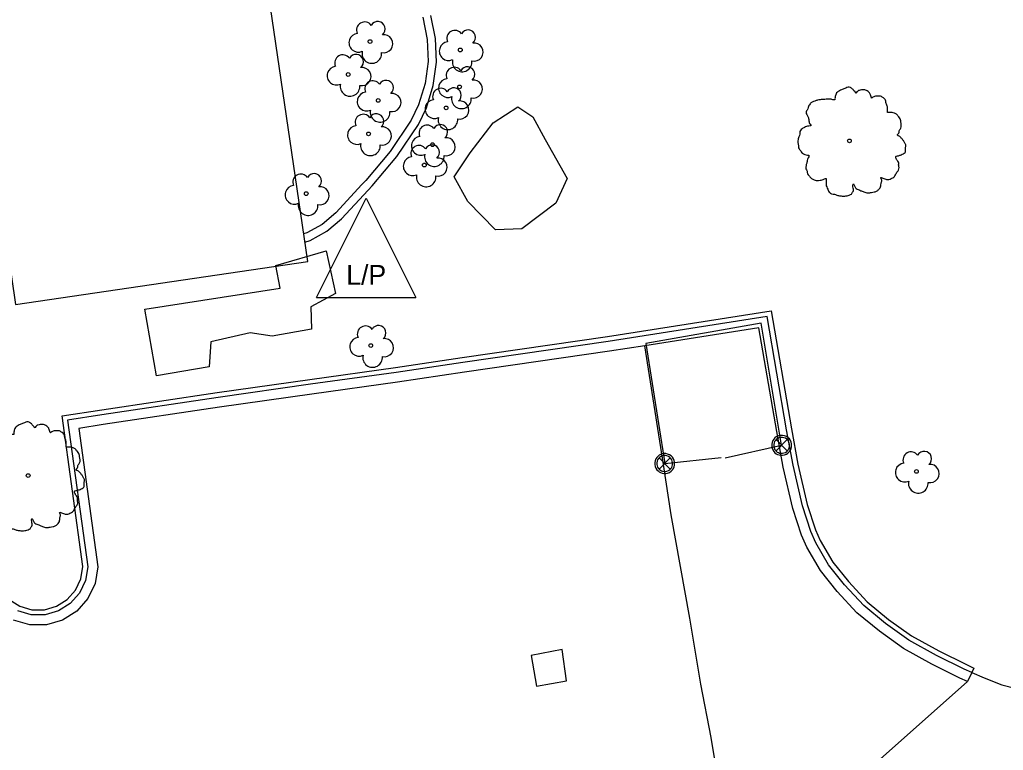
# Model space of a CAD drawing. Extents: x 2161152 to 2175754, y 602179 to 617749.
# Drawn here: x 2163635 to 2163733.9, y 606221.2 to 606294.7 of the extents above; entities that cross this region are included whole.
import ezdxf

# ---------------------------------------------------------------- set-up
doc = ezdxf.new("R2010")
doc.units = 0
for name, color, linetype in [('RD_EX_Bldg', 7, 'Continuous'), ('RD_EX_BldgApp_Post', 7, 'Continuous'), ('RD_EX_Conc_Curb', 7, 'Continuous'), ('RD_EX_Conc_Gutter', 7, 'Continuous'), ('RD_EX_DR_Inlet', 7, 'Continuous'), ('RD_EX_Fence_ChLk', 7, 'Continuous'), ('RD_EX_Fence_Gate', 7, 'Continuous'), ('RD_EX_Parking_Asphalt', 7, 'Continuous'), ('RD_EX_Parking_Conc', 7, 'Continuous'), ('RD_EX_UT', 7, 'Continuous'), ('RD_EX_VEG', 7, 'Continuous'), ('RD_EX_WALL_Retaining', 7, 'Continuous')]:
    doc.layers.add(name, color=color, linetype=linetype)

msp = doc.modelspace()

# ---------------------------------------------------------------- linework, layer by layer
at = {"layer": 'RD_EX_Bldg'}
msp.add_lwpolyline([(2163498.737, 606320.775), (2163509.48, 606247.58), (2163538.628, 606251.858), (2163536.268, 606267.933), (2163632.211, 606282.015), (2163634.559, 606266.023), (2163663.946, 606270.336), (2163653.216, 606343.448), (2163498.737, 606320.775)], dxfattribs=at)
at = {"layer": 'RD_EX_BldgApp_Post'}
for p, q in [((2163712.191, 606251.292), (2163711.057, 606252.426)), ((2163711.057, 606251.292), (2163712.191, 606252.426)), ((2163700.425, 606249.454), (2163699.291, 606250.588)), ((2163699.291, 606249.454), (2163700.425, 606250.588))]:
    msp.add_line(p, q, dxfattribs=at)
for points in [[(2163712.626, 606251.859), (2163712.614, 606252.013), (2163712.575, 606252.176), (2163712.503, 606252.34), (2163712.398, 606252.495), (2163712.26, 606252.633), (2163712.096, 606252.743), (2163711.914, 606252.818), (2163711.725, 606252.856), (2163711.54, 606252.858), (2163711.367, 606252.828), (2163711.213, 606252.773), (2163711.079, 606252.701), (2163710.953, 606252.604), (2163710.836, 606252.479), (2163710.737, 606252.326), (2163710.664, 606252.15), (2163710.626, 606251.958), (2163710.626, 606251.76), (2163710.664, 606251.567), (2163710.737, 606251.391), (2163710.836, 606251.239), (2163710.953, 606251.114), (2163711.079, 606251.017), (2163711.213, 606250.944), (2163711.367, 606250.89), (2163711.54, 606250.86), (2163711.725, 606250.861), (2163711.914, 606250.899), (2163712.096, 606250.974), (2163712.26, 606251.084), (2163712.398, 606251.222), (2163712.503, 606251.378), (2163712.575, 606251.542), (2163712.614, 606251.704), (2163712.626, 606251.859)], [(2163712.426, 606251.859), (2163712.416, 606251.982), (2163712.384, 606252.112), (2163712.327, 606252.243), (2163712.243, 606252.368), (2163712.133, 606252.478), (2163712.001, 606252.566), (2163711.856, 606252.626), (2163711.705, 606252.656), (2163711.556, 606252.658), (2163711.418, 606252.634), (2163711.295, 606252.59), (2163711.188, 606252.532), (2163711.087, 606252.455), (2163710.994, 606252.355), (2163710.914, 606252.233), (2163710.856, 606252.092), (2163710.826, 606251.938), (2163710.826, 606251.78), (2163710.856, 606251.626), (2163710.914, 606251.485), (2163710.994, 606251.363), (2163711.087, 606251.263), (2163711.188, 606251.185), (2163711.295, 606251.127), (2163711.418, 606251.083), (2163711.556, 606251.06), (2163711.705, 606251.061), (2163711.856, 606251.091), (2163712.001, 606251.151), (2163712.133, 606251.239), (2163712.243, 606251.349), (2163712.327, 606251.474), (2163712.384, 606251.605), (2163712.416, 606251.735), (2163712.426, 606251.859)], [(2163700.861, 606250.021), (2163700.849, 606250.176), (2163700.809, 606250.339), (2163700.738, 606250.502), (2163700.633, 606250.658), (2163700.495, 606250.796), (2163700.331, 606250.906), (2163700.148, 606250.981), (2163699.959, 606251.019), (2163699.774, 606251.02), (2163699.602, 606250.99), (2163699.448, 606250.936), (2163699.314, 606250.863), (2163699.188, 606250.767), (2163699.071, 606250.641), (2163698.972, 606250.489), (2163698.899, 606250.313), (2163698.861, 606250.12), (2163698.861, 606249.922), (2163698.899, 606249.73), (2163698.972, 606249.554), (2163699.071, 606249.401), (2163699.188, 606249.276), (2163699.314, 606249.18), (2163699.448, 606249.107), (2163699.602, 606249.052), (2163699.774, 606249.023), (2163699.959, 606249.024), (2163700.148, 606249.062), (2163700.331, 606249.137), (2163700.495, 606249.247), (2163700.633, 606249.385), (2163700.738, 606249.54), (2163700.809, 606249.704), (2163700.849, 606249.867), (2163700.861, 606250.021)], [(2163700.66, 606250.021), (2163700.651, 606250.145), (2163700.619, 606250.275), (2163700.562, 606250.406), (2163700.478, 606250.531), (2163700.368, 606250.641), (2163700.236, 606250.729), (2163700.09, 606250.789), (2163699.939, 606250.819), (2163699.791, 606250.821), (2163699.653, 606250.797), (2163699.53, 606250.753), (2163699.423, 606250.695), (2163699.322, 606250.617), (2163699.228, 606250.517), (2163699.149, 606250.395), (2163699.091, 606250.254), (2163699.06, 606250.101), (2163699.06, 606249.942), (2163699.091, 606249.788), (2163699.149, 606249.647), (2163699.228, 606249.525), (2163699.322, 606249.425), (2163699.423, 606249.348), (2163699.53, 606249.29), (2163699.653, 606249.246), (2163699.791, 606249.222), (2163699.939, 606249.224), (2163700.09, 606249.254), (2163700.236, 606249.314), (2163700.368, 606249.402), (2163700.478, 606249.512), (2163700.562, 606249.637), (2163700.619, 606249.768), (2163700.651, 606249.898), (2163700.66, 606250.021)]]:
    msp.add_lwpolyline(points, dxfattribs=at)
at = {"layer": 'RD_EX_Conc_Curb'}
for points in [[(2163633.915, 606236.335), (2163634.984, 606235.665), (2163636.196, 606235.317), (2163637.457, 606235.318), (2163638.669, 606235.668), (2163639.736, 606236.34), (2163640.575, 606237.282), (2163641.121, 606238.419), (2163641.329, 606239.656), (2163639.232, 606254.817), (2163643.225, 606255.429), (2163654.854, 606257.168), (2163664.155, 606258.492), (2163672.772, 606259.69), (2163679.494, 606260.684), (2163694.091, 606262.798), (2163710.561, 606265.383), (2163712.604, 606253.505), (2163713.261, 606249.97), (2163714.195, 606245.894), (2163715.034, 606243.372), (2163715.508, 606242.282), (2163716.758, 606240.115), (2163718.336, 606238.149), (2163720.224, 606236.108), (2163722.373, 606234.344), (2163724.676, 606232.7), (2163727.444, 606231.177), (2163730.204, 606229.806), (2163730.963, 606229.456), (2163730.754, 606229.002)], [(2163730.754, 606229.002), (2163729.989, 606229.355), (2163727.213, 606230.733), (2163724.409, 606232.276), (2163722.068, 606233.947), (2163719.88, 606235.744), (2163717.958, 606237.823), (2163716.344, 606239.831), (2163715.06, 606242.057), (2163714.567, 606243.194), (2163713.713, 606245.759), (2163712.771, 606249.868), (2163712.112, 606253.417), (2163710.152, 606264.812), (2163694.165, 606262.303), (2163679.567, 606260.189), (2163672.843, 606259.195), (2163664.225, 606257.996), (2163654.926, 606256.673), (2163643.23, 606254.924), (2163639.795, 606254.398), (2163641.835, 606239.649), (2163641.602, 606238.266), (2163640.995, 606237.002), (2163640.062, 606235.955), (2163638.876, 606235.207), (2163637.528, 606234.818), (2163636.126, 606234.816), (2163634.778, 606235.203)]]:
    msp.add_lwpolyline(points, dxfattribs=at)
at = {"layer": 'RD_EX_Conc_Gutter'}
msp.add_lwpolyline([(2163730.754, 606229.002), (2163730.335, 606228.094), (2163729.557, 606228.453), (2163726.749, 606229.847), (2163723.876, 606231.428), (2163721.46, 606233.153), (2163719.193, 606235.014), (2163717.2, 606237.169), (2163715.517, 606239.265), (2163714.166, 606241.607), (2163713.632, 606242.836), (2163712.749, 606245.489), (2163711.791, 606249.665), (2163711.127, 606253.241), (2163709.334, 606263.672), (2163697.858, 606261.871), (2163694.314, 606261.315), (2163679.711, 606259.2), (2163672.985, 606258.205), (2163664.364, 606257.006), (2163655.07, 606255.684), (2163643.381, 606253.935), (2163640.921, 606253.558), (2163642.847, 606239.634), (2163642.565, 606237.961), (2163641.836, 606236.442), (2163640.715, 606235.184), (2163639.289, 606234.286), (2163637.671, 606233.818), (2163635.986, 606233.816), (2163634.366, 606234.281)], dxfattribs=at)
at = {"layer": 'RD_EX_DR_Inlet'}
msp.add_lwpolyline([(2163686.439, 606230.705), (2163686.967, 606227.645), (2163689.979, 606228.165), (2163689.56, 606231.31), (2163686.439, 606230.705)], dxfattribs=at)
at = {"layer": 'RD_EX_Fence_ChLk'}
msp.add_lwpolyline([(2163711.624, 606251.859), (2163709.559, 606264.125), (2163697.954, 606262.1), (2163699.858, 606250.021)], dxfattribs=at)
at = {"layer": 'RD_EX_Fence_Gate'}
for p, q in [((2163705.952, 606250.605), (2163711.624, 606251.859)), ((2163699.858, 606250.021), (2163705.556, 606250.626))]:
    msp.add_line(p, q, dxfattribs=at)
at = {"layer": 'RD_EX_Parking_Asphalt'}
msp.add_lwpolyline([(2163730.754, 606229.002), (2163731.998, 606228.461), (2163733.791, 606227.776), (2163736.519, 606227.078), (2163738.725, 606226.876), (2163741.682, 606226.826), (2163744.188, 606226.765), (2163746.812, 606226.609), (2163748.382, 606226.712), (2163749.856, 606227.167), (2163751.292, 606227.813), (2163753.161, 606228.618)], dxfattribs=at)
at = {"layer": 'RD_EX_Parking_Conc'}
for points in [[(2163705.32, 606217.804), (2163704.529, 606222.462), (2163703.508, 606227.844), (2163702.398, 606234.461), (2163700.511, 606244.882), (2163699.752, 606249.926), (2163697.858, 606261.871)], [(2163730.335, 606228.094), (2163720.342, 606219.231), (2163711.857, 606211.684)]]:
    msp.add_lwpolyline(points, dxfattribs=at)
at = {"layer": 'RD_EX_UT'}
for p, q in [((2163664.836, 606266.716), (2163669.836, 606276.716)), ((2163669.836, 606276.716), (2163674.836, 606266.716)), ((2163664.836, 606266.716), (2163674.836, 606266.716))]:
    msp.add_line(p, q, dxfattribs=at)
at = {"layer": 'RD_EX_VEG'}
for points in [[(2163690.033, 606278.684), (2163688.894, 606276.222), (2163685.488, 606273.616), (2163682.834, 606273.522), (2163680.057, 606276.391), (2163678.68, 606278.852), (2163680.281, 606281.261), (2163682.617, 606284.286), (2163685.084, 606285.895), (2163686.583, 606284.902), (2163687.829, 606282.62), (2163690.033, 606278.684)], [(2163658.147, 606263.173), (2163654.189, 606262.266), (2163654.036, 606259.753), (2163648.742, 606258.829), (2163647.569, 606265.544), (2163661.167, 606267.67), (2163660.732, 606269.929), (2163665.791, 606271.423), (2163666.747, 606267.135), (2163664.266, 606265.776), (2163664.335, 606263.547), (2163660.382, 606262.834), (2163658.147, 606263.173)]]:
    msp.add_lwpolyline(points, dxfattribs=at)
for centre, radius in [((2163670.216, 606292.458), 0.188), ((2163679.3, 606291.614), 0.188), ((2163668.022, 606289.15), 0.188), ((2163679.227, 606287.898), 0.188), ((2163671.045, 606286.539), 0.188), ((2163677.868, 606285.789), 0.188), ((2163670.071, 606283.175), 0.188), ((2163718.445, 606282.468), 0.188), ((2163718.435, 606282.454), 0.000075), ((2163676.497, 606282.093), 0.188), ((2163675.68, 606280.045), 0.188), ((2163663.8, 606277.166), 0.188), ((2163670.291, 606261.887), 0.188), ((2163635.828, 606248.811), 0.188), ((2163635.819, 606248.797), 0.000075), ((2163725.182, 606249.231), 0.188)]:
    msp.add_circle(centre, radius, dxfattribs=at)
for centre, radius, start, end in [((2163669.675, 606293.619), 0.813, 34.97629, 204.75602), ((2163671, 606293.735), 0.746, 308.76261, 152.04674), ((2163669.043, 606292.342), 0.943, 96.45179, 294.73401), ((2163678.759, 606292.774), 0.813, 34.97629, 204.75602), ((2163680.084, 606292.89), 0.746, 308.76261, 152.04674), ((2163671.596, 606292.249), 0.914, 256.56668, 98.10463), ((2163678.127, 606291.497), 0.943, 96.45179, 294.73401), ((2163680.68, 606291.404), 0.914, 256.56668, 98.10463), ((2163670.4, 606291.261), 0.988, 166.88266, 5.75893), ((2163667.481, 606290.311), 0.813, 34.97629, 204.75602), ((2163668.806, 606290.427), 0.746, 308.76261, 152.04674), ((2163679.484, 606290.416), 0.988, 166.88266, 5.75893), ((2163666.849, 606289.034), 0.943, 96.45179, 294.73401), ((2163669.402, 606288.941), 0.914, 256.56668, 98.10463), ((2163678.686, 606289.059), 0.813, 34.97629, 204.75602), ((2163680.011, 606289.175), 0.746, 308.76261, 152.04674), ((2163670.504, 606287.699), 0.813, 34.97629, 204.75602), ((2163671.829, 606287.815), 0.746, 308.76261, 152.04674), ((2163678.054, 606287.782), 0.943, 96.45179, 294.73401), ((2163680.607, 606287.689), 0.914, 256.56668, 98.10463), ((2163668.206, 606287.953), 0.988, 166.88266, 5.75893), ((2163669.872, 606286.422), 0.943, 96.45179, 294.73401), ((2163672.425, 606286.329), 0.914, 256.56668, 98.10463), ((2163677.327, 606286.95), 0.813, 34.97629, 204.75602), ((2163678.651, 606287.066), 0.746, 308.76261, 152.04674), ((2163676.695, 606285.673), 0.943, 96.45179, 294.73401), ((2163679.411, 606286.701), 0.988, 166.88266, 5.75893), ((2163679.247, 606285.58), 0.914, 256.56668, 98.10463), ((2163671.229, 606285.341), 0.988, 166.88266, 5.75893), ((2163669.531, 606284.336), 0.813, 34.97629, 204.75602), ((2163670.855, 606284.452), 0.746, 308.76261, 152.04674), ((2163678.052, 606284.592), 0.988, 166.88266, 5.75893), ((2163668.899, 606283.059), 0.943, 96.45179, 294.73401), ((2163671.451, 606282.966), 0.914, 256.56668, 98.10463), ((2163675.956, 606283.254), 0.813, 34.97629, 204.75602), ((2163677.281, 606283.37), 0.746, 308.76261, 152.04674), ((2163675.324, 606281.976), 0.943, 96.45179, 294.73401), ((2163677.877, 606281.884), 0.914, 256.56668, 98.10463), ((2163670.256, 606281.978), 0.988, 166.88266, 5.75893), ((2163675.14, 606281.206), 0.813, 34.97629, 204.75602), ((2163676.464, 606281.322), 0.746, 308.76261, 152.04674), ((2163674.508, 606279.929), 0.943, 96.45179, 294.73401), ((2163676.681, 606280.896), 0.988, 166.88266, 5.75893), ((2163677.06, 606279.836), 0.914, 256.56668, 98.10463), ((2163663.259, 606278.326), 0.813, 34.97629, 204.75602), ((2163664.584, 606278.443), 0.746, 308.76261, 152.04674), ((2163675.864, 606278.848), 0.988, 166.88266, 5.75893), ((2163662.627, 606277.049), 0.943, 96.45179, 294.73401), ((2163665.18, 606276.956), 0.914, 256.56668, 98.10463), ((2163663.984, 606275.969), 0.988, 166.88266, 5.75893), ((2163669.75, 606263.048), 0.813, 34.97629, 204.75602), ((2163671.075, 606263.164), 0.746, 308.76261, 152.04674), ((2163669.118, 606261.771), 0.943, 96.45179, 294.73401), ((2163671.671, 606261.678), 0.914, 256.56668, 98.10463), ((2163670.475, 606260.69), 0.988, 166.88266, 5.75893), ((2163724.641, 606250.391), 0.813, 34.97629, 204.75602), ((2163725.966, 606250.508), 0.746, 308.76261, 152.04674), ((2163724.009, 606249.114), 0.943, 96.45179, 294.73401), ((2163726.561, 606249.022), 0.914, 256.56668, 98.10463), ((2163725.366, 606248.034), 0.988, 166.88266, 5.75893)]:
    msp.add_arc(centre, radius, start, end, dxfattribs=at)
for points in [[(2163718.544, 606287.843), (2163718.319, 606287.862), (2163718.075, 606287.787), (2163717.888, 606287.712), (2163717.719, 606287.656), (2163717.55, 606287.581), (2163717.325, 606287.45), (2163717.157, 606287.3), (2163717.063, 606287.112), (2163717.025, 606286.944), (2163716.988, 606286.737), (2163716.988, 606286.606), (2163716.894, 606286.587), (2163716.782, 606286.606), (2163716.594, 606286.662), (2163716.407, 606286.662), (2163716.22, 606286.662), (2163715.957, 606286.644), (2163715.695, 606286.644), (2163715.489, 606286.606), (2163715.245, 606286.569), (2163714.964, 606286.475), (2163714.701, 606286.381), (2163714.477, 606286.194), (2163714.289, 606285.838), (2163714.195, 606285.575), (2163714.083, 606285.388), (2163714.195, 606285.051), (2163714.327, 606284.788), (2163714.345, 606284.638), (2163714.402, 606284.32), (2163714.477, 606284.151), (2163714.57, 606284.001), (2163714.514, 606283.982), (2163714.233, 606283.945), (2163714.008, 606283.87), (2163713.689, 606283.701), (2163713.521, 606283.533), (2163713.446, 606283.289), (2163713.427, 606283.027), (2163713.352, 606282.877), (2163713.296, 606282.67), (2163713.277, 606282.614), (2163713.24, 606282.371), (2163713.315, 606282.033), (2163713.333, 606281.771), (2163713.427, 606281.602), (2163713.539, 606281.471), (2163713.671, 606281.284), (2163713.971, 606281.115), (2163714.214, 606281.04), (2163714.364, 606281.021), (2163714.233, 606280.646), (2163714.195, 606280.384), (2163714.102, 606280.084), (2163714.102, 606280.028), (2163714.064, 606279.672), (2163714.177, 606279.428), (2163714.233, 606279.147), (2163714.364, 606278.978), (2163714.57, 606278.753), (2163714.814, 606278.585), (2163715.189, 606278.491), (2163715.489, 606278.51), (2163715.92, 606278.641), (2163716.107, 606278.697), (2163716.088, 606278.566), (2163716.107, 606278.285), (2163716.107, 606277.966), (2163716.22, 606277.723), (2163716.295, 606277.516), (2163716.407, 606277.329), (2163716.651, 606277.16), (2163716.95, 606277.104), (2163717.269, 606276.992), (2163717.606, 606276.935), (2163717.981, 606276.917), (2163718.431, 606277.029), (2163718.637, 606277.123), (2163718.712, 606277.254), (2163718.862, 606277.535), (2163718.825, 606277.704), (2163718.843, 606278.154), (2163718.918, 606278.022), (2163719.05, 606277.76), (2163719.424, 606277.535), (2163719.724, 606277.404), (2163720.08, 606277.292), (2163720.305, 606277.235), (2163720.661, 606277.292), (2163720.943, 606277.348), (2163721.224, 606277.442), (2163721.449, 606277.648), (2163721.58, 606277.854), (2163721.617, 606278.06), (2163721.673, 606278.341), (2163721.711, 606278.472)], [(2163721.711, 606278.472), (2163721.655, 606278.604), (2163721.617, 606278.791), (2163721.673, 606278.772), (2163721.805, 606278.735), (2163722.011, 606278.641), (2163722.179, 606278.585), (2163722.423, 606278.604), (2163722.629, 606278.678), (2163722.967, 606278.885), (2163723.173, 606279.241), (2163723.379, 606279.541), (2163723.435, 606279.784), (2163723.398, 606279.953), (2163723.379, 606280.328), (2163723.229, 606280.515), (2163723.191, 606280.609), (2163723.117, 606280.909), (2163723.173, 606280.946), (2163723.379, 606280.984), (2163723.66, 606281.077), (2163723.866, 606281.171), (2163724.035, 606281.302), (2163724.091, 606281.471), (2163724.072, 606281.771), (2163724.11, 606282.071), (2163724.054, 606282.183), (2163723.979, 606282.296), (2163723.922, 606282.446), (2163723.81, 606282.558), (2163723.735, 606282.67), (2163723.66, 606282.745), (2163723.566, 606282.858), (2163723.435, 606282.952), (2163723.323, 606282.989), (2163723.285, 606283.102), (2163723.398, 606283.251), (2163723.435, 606283.326), (2163723.454, 606283.495), (2163723.623, 606283.757), (2163723.66, 606284.057), (2163723.623, 606284.376), (2163723.585, 606284.582), (2163723.473, 606284.788), (2163723.323, 606284.976), (2163723.229, 606285.107), (2163723.098, 606285.201), (2163722.854, 606285.294), (2163722.667, 606285.332), (2163722.404, 606285.332), (2163722.254, 606285.369), (2163722.273, 606285.407), (2163722.273, 606285.519), (2163722.273, 606285.725), (2163722.217, 606286.063), (2163722.104, 606286.438), (2163722.104, 606286.456), (2163722.029, 606286.644), (2163721.861, 606286.794), (2163721.73, 606286.869), (2163721.58, 606286.962), (2163721.392, 606286.981), (2163721.167, 606286.981), (2163720.961, 606286.944), (2163720.811, 606286.869), (2163720.68, 606286.775), (2163720.624, 606286.887), (2163720.549, 606287.112), (2163720.511, 606287.225), (2163720.399, 606287.356), (2163720.23, 606287.506), (2163719.893, 606287.6), (2163719.424, 606287.543), (2163719.199, 606287.393), (2163719.087, 606287.262), (2163719.05, 606287.356), (2163718.9, 606287.506), (2163718.825, 606287.637), (2163718.693, 606287.731), (2163718.581, 606287.806), (2163718.506, 606287.843)], [(2163635.927, 606254.187), (2163635.702, 606254.206), (2163635.459, 606254.131), (2163635.271, 606254.056), (2163635.103, 606253.999), (2163634.934, 606253.924), (2163634.709, 606253.793), (2163634.54, 606253.643), (2163634.447, 606253.456), (2163634.409, 606253.287), (2163634.372, 606253.081), (2163634.372, 606252.95), (2163634.278, 606252.931), (2163634.165, 606252.95), (2163633.978, 606253.006), (2163633.791, 606253.006), (2163633.603, 606253.006), (2163633.341, 606252.987), (2163633.078, 606252.987), (2163632.872, 606252.95), (2163632.629, 606252.912), (2163632.347, 606252.819), (2163632.085, 606252.725), (2163631.86, 606252.538), (2163631.673, 606252.182), (2163631.579, 606251.919), (2163631.467, 606251.732), (2163631.579, 606251.394), (2163631.71, 606251.132), (2163631.729, 606250.982), (2163631.785, 606250.663), (2163631.86, 606250.495), (2163631.954, 606250.345), (2163631.898, 606250.326), (2163631.617, 606250.289), (2163631.392, 606250.214), (2163631.073, 606250.045), (2163630.904, 606249.876), (2163630.829, 606249.633), (2163630.811, 606249.37), (2163630.736, 606249.22), (2163630.679, 606249.014), (2163630.661, 606248.958), (2163630.623, 606248.714), (2163630.698, 606248.377), (2163630.717, 606248.115), (2163630.811, 606247.946), (2163630.923, 606247.815), (2163631.054, 606247.627), (2163631.354, 606247.459), (2163631.598, 606247.384), (2163631.748, 606247.365), (2163631.617, 606246.99), (2163631.579, 606246.728), (2163631.485, 606246.428), (2163631.485, 606246.372), (2163631.448, 606246.015), (2163631.56, 606245.772), (2163631.617, 606245.491), (2163631.748, 606245.322), (2163631.954, 606245.097), (2163632.198, 606244.928), (2163632.572, 606244.835), (2163632.872, 606244.853), (2163633.303, 606244.985), (2163633.491, 606245.041), (2163633.472, 606244.91), (2163633.491, 606244.629), (2163633.491, 606244.31), (2163633.603, 606244.066), (2163633.678, 606243.86), (2163633.791, 606243.673), (2163634.034, 606243.504), (2163634.334, 606243.448), (2163634.653, 606243.335), (2163634.99, 606243.279), (2163635.365, 606243.26), (2163635.815, 606243.373), (2163636.021, 606243.467), (2163636.096, 606243.598), (2163636.246, 606243.879), (2163636.208, 606244.048), (2163636.227, 606244.497), (2163636.302, 606244.366), (2163636.433, 606244.104), (2163636.808, 606243.879), (2163637.108, 606243.748), (2163637.464, 606243.635), (2163637.689, 606243.579), (2163638.045, 606243.635), (2163638.326, 606243.691), (2163638.607, 606243.785), (2163638.832, 606243.991), (2163638.963, 606244.198), (2163639.001, 606244.404), (2163639.057, 606244.685), (2163639.095, 606244.816)], [(2163639.095, 606244.816), (2163639.038, 606244.947), (2163639.001, 606245.135), (2163639.057, 606245.116), (2163639.188, 606245.078), (2163639.394, 606244.985), (2163639.563, 606244.928), (2163639.807, 606244.947), (2163640.013, 606245.022), (2163640.35, 606245.228), (2163640.556, 606245.584), (2163640.763, 606245.884), (2163640.819, 606246.128), (2163640.781, 606246.297), (2163640.763, 606246.671), (2163640.613, 606246.859), (2163640.575, 606246.953), (2163640.5, 606247.252), (2163640.556, 606247.29), (2163640.763, 606247.327), (2163641.044, 606247.421), (2163641.25, 606247.515), (2163641.419, 606247.646), (2163641.475, 606247.815), (2163641.456, 606248.115), (2163641.493, 606248.414), (2163641.437, 606248.527), (2163641.362, 606248.639), (2163641.306, 606248.789), (2163641.194, 606248.902), (2163641.119, 606249.014), (2163641.044, 606249.089), (2163640.95, 606249.202), (2163640.819, 606249.295), (2163640.706, 606249.333), (2163640.669, 606249.445), (2163640.781, 606249.595), (2163640.819, 606249.67), (2163640.837, 606249.839), (2163641.006, 606250.101), (2163641.044, 606250.401), (2163641.006, 606250.72), (2163640.969, 606250.926), (2163640.856, 606251.132), (2163640.706, 606251.319), (2163640.613, 606251.451), (2163640.481, 606251.544), (2163640.238, 606251.638), (2163640.05, 606251.675), (2163639.788, 606251.675), (2163639.638, 606251.713), (2163639.657, 606251.75), (2163639.657, 606251.863), (2163639.657, 606252.069), (2163639.601, 606252.406), (2163639.488, 606252.781), (2163639.488, 606252.8), (2163639.413, 606252.987), (2163639.244, 606253.137), (2163639.113, 606253.212), (2163638.963, 606253.306), (2163638.776, 606253.325), (2163638.551, 606253.325), (2163638.345, 606253.287), (2163638.195, 606253.212), (2163638.064, 606253.119), (2163638.007, 606253.231), (2163637.933, 606253.456), (2163637.895, 606253.568), (2163637.783, 606253.7), (2163637.614, 606253.85), (2163637.277, 606253.943), (2163636.808, 606253.887), (2163636.583, 606253.737), (2163636.471, 606253.606), (2163636.433, 606253.7), (2163636.283, 606253.85), (2163636.208, 606253.981), (2163636.077, 606254.074), (2163635.965, 606254.149), (2163635.89, 606254.187)]]:
    msp.add_spline(points, degree=3, dxfattribs=at)
at = {"layer": 'RD_EX_WALL_Retaining'}
for points in [[(2163675.521, 606294.909), (2163675.979, 606292.668), (2163676.056, 606290.442), (2163675.763, 606288.235), (2163675.106, 606286.099), (2163674.362, 606284.545), (2163672.24, 606281.419), (2163669.792, 606278.491), (2163669.405, 606278.078), (2163666.773, 606275.228), (2163665.41, 606274.066), (2163663.871, 606273.218), (2163663.539, 606273.116)], [(2163663.661, 606272.281), (2163664.199, 606272.448), (2163665.887, 606273.377), (2163667.351, 606274.626), (2163670.015, 606277.51), (2163670.416, 606277.938), (2163672.906, 606280.917), (2163675.086, 606284.128), (2163675.885, 606285.795), (2163676.58, 606288.056), (2163676.891, 606290.402), (2163676.809, 606292.766), (2163676.336, 606295.084)]]:
    msp.add_lwpolyline(points, dxfattribs=at)

# ---------------------------------------------------------------- texts
at = {"layer": 'RD_EX_UT'}
msp.add_text('L/P', height=2, dxfattribs=at).set_placement((2163667.827, 606267.997))

doc.saveas('drawing.dxf')
